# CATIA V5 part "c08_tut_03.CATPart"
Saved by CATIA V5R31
Part number: Boolean
Bounding box of the stored display mesh (mm): x -54.918 to 54.918, y -54.918 to 54.918, z -5 to 100
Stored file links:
  D:\PROJECTS\Project 2021\US EDITION\CATIA V5 6R 2021\Resources\Tutorial Files\c08_catia_v5_6r2021_tut\c08_tut_03.CATPart
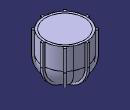
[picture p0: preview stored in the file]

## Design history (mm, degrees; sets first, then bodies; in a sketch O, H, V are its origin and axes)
Body1 (main body)
Body2 "Result"
  Body3 "Material_addition"
    Body4 "Base_feature"
      Solid1: linked copy from another document
    Add1: tool Body4
    Body5 "Rib"
      Solid2: linked copy from another document
      Thickness1: Thickness 1
      Body6 "Rib_plates"
        Sketch1 on face of Solid2, origin (0, 0, 100), H (1, 0, 0), V (0, 1, 0)
          line L1 (0, 0) -> (0, 73.1213)
          vertical: L1 V
        Pad1: profile Sketch1, direction (0, 0, 1), length 20, opposite side length 125, thin wall 6
        CircPattern1: of Pad1, instances 8, angular step 45 {= 360.0*1 deg/CircPattern1.AngularNumber}, axis from Z axis
      Intersect1: tool Body6
    Add2: tool Body5
  Add3: tool Body3
  Body7 "Material_removal"
    Body8 "core"
      Solid3: linked copy from another document
      Thickness2: Thickness 1
    Add4: tool Body8
  Remove1: tool Body7
Body9 "Base_feature"
  Sketch2 on yz-plane, origin (0, 0, 0), H (0, 1, 0), V (0, 0, 1)
    line L1 (0, 0) -> (0, 100)
    line L2 (0, 100) -> (50, 100)
    line L3 (50, 100) -> (50, 50)
    arc A1 centre (0, 50) radius 50 from (50, 50) to (0, 0) cw
    axis line L4 (0, 116.7367) -> (0, -14.1151)
    point P5 (0, 116.7367)
    point P6 (0, -14.1151)
    length L1 = 100
    length L2 = 50
    vertical: L1 V, L3 V, L4 V
    horizontal: L2 H
    tangency: A1 L3, A1 H
    coincidence: P5 V, P5 L1, P6 V
  Shaft1: profile Sketch2, axis Sketch2.L1, angle 360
